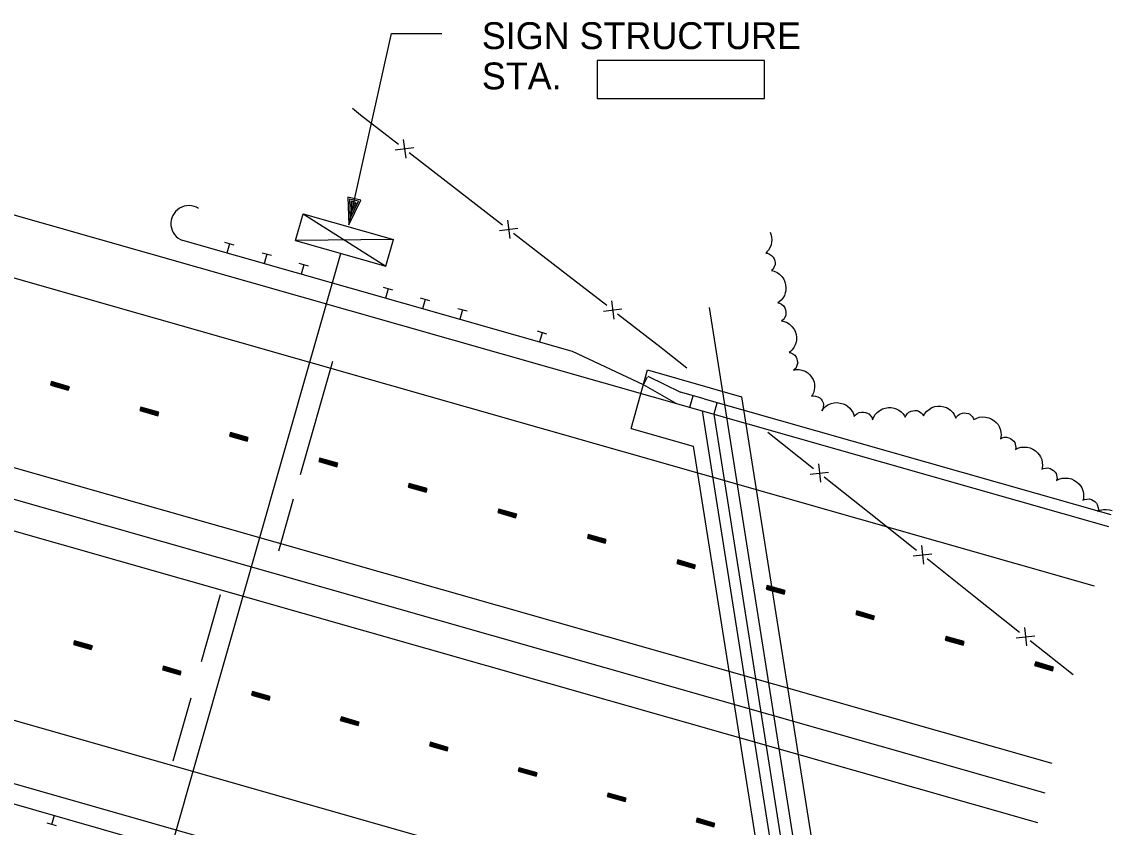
# Model space of a CAD drawing. Extents: x 640117 to 642655, y 297247 to 298435.
# Drawn here: x 641580.9 to 641702.7, y 298034.9 to 298124.9 of the extents above; entities that cross this region are included whole.
import ezdxf

# ---------------------------------------------------------------- set-up
doc = ezdxf.new("R2010")
doc.units = 0
for name, color, linetype in [('2', 7, 'Continuous'), ('20', 7, 'Continuous'), ('21', 7, 'Continuous'), ('26', 7, 'Continuous'), ('27', 7, 'Continuous'), ('36', 7, 'Continuous'), ('43', 7, 'Continuous'), ('48', 7, 'Continuous'), ('50', 7, 'Continuous'), ('51', 7, 'Continuous'), ('52', 7, 'Continuous'), ('7', 7, 'Continuous')]:
    doc.layers.add(name, color=color, linetype=linetype)

msp = doc.modelspace()

# ---------------------------------------------------------------- linework, layer by layer
at = {"layer": '2'}
msp.add_lwpolyline([(641645.15, 298116.37), (641663.87, 298116.37), (641663.87, 298120.62), (641645.15, 298120.62)], close=True, dxfattribs=at)
at = {"layer": '20'}
for points in [[(641664.48, 298101.43), (641664.57, 298101.21), (641664.65, 298100.88), (641664.69, 298100.56), (641664.66, 298100.33), (641664.59, 298100.01), (641664.46, 298099.69), (641664.3, 298099.43), (641664.13, 298099.23), (641664, 298099.1), (641664.18, 298099.08), (641664.42, 298098.99), (641664.64, 298098.84), (641664.82, 298098.64), (641664.93, 298098.45), (641665, 298098.24), (641665.05, 298097.99), (641665.04, 298097.81), (641664.92, 298097.47), (641664.83, 298097.29), (641664.66, 298097.14)], [(641664.66, 298097.14), (641664.95, 298097.06), (641665.28, 298096.91), (641665.53, 298096.73), (641665.8, 298096.46), (641666.01, 298096.17), (641666.14, 298095.88), (641666.22, 298095.54), (641666.26, 298095.21), (641666.25, 298094.88), (641666.19, 298094.66), (641666.08, 298094.36), (641665.91, 298094.06), (641665.71, 298093.82), (641665.51, 298093.64), (641665.37, 298093.54), (641665.54, 298093.49), (641665.77, 298093.37), (641665.97, 298093.19), (641666.12, 298092.98), (641666.2, 298092.77), (641666.24, 298092.55), (641666.26, 298092.3), (641666.23, 298092.13), (641666.06, 298091.8), (641665.94, 298091.64), (641665.76, 298091.51)], [(641665.76, 298091.51), (641666.05, 298091.46), (641666.38, 298091.33), (641666.64, 298091.15), (641666.92, 298090.9), (641667.15, 298090.62), (641667.29, 298090.35), (641667.39, 298090.01), (641667.43, 298089.69), (641667.44, 298089.37), (641667.4, 298089.14), (641667.29, 298088.84), (641667.13, 298088.54), (641666.95, 298088.29), (641666.76, 298088.11), (641666.61, 298088), (641666.79, 298087.96), (641667.03, 298087.85), (641667.24, 298087.69), (641667.39, 298087.48), (641667.49, 298087.28), (641667.53, 298087.07), (641667.57, 298086.83), (641667.53, 298086.65), (641667.39, 298086.32), (641667.28, 298086.16), (641667.1, 298086.02)], [(641667.1, 298086.02), (641667.39, 298086.07), (641667.74, 298086.08), (641668.05, 298086.01), (641668.4, 298085.88), (641668.71, 298085.7), (641668.93, 298085.5), (641669.13, 298085.23), (641669.29, 298084.95), (641669.41, 298084.66), (641669.45, 298084.43), (641669.46, 298084.12), (641669.42, 298083.79), (641669.33, 298083.49), (641669.22, 298083.26), (641669.12, 298083.11), (641669.3, 298083.13), (641669.56, 298083.11), (641669.81, 298083.04), (641670.03, 298082.91), (641670.18, 298082.76), (641670.3, 298082.59), (641670.41, 298082.37), (641670.45, 298082.2), (641670.42, 298081.84), (641670.38, 298081.65), (641670.26, 298081.47)], [(641670.26, 298081.47), (641670.43, 298081.7), (641670.69, 298081.96), (641670.95, 298082.13), (641671.3, 298082.28), (641671.66, 298082.37), (641671.98, 298082.39), (641672.33, 298082.34), (641672.65, 298082.25), (641672.95, 298082.13), (641673.14, 298081.99), (641673.38, 298081.78), (641673.6, 298081.51), (641673.75, 298081.24), (641673.85, 298081), (641673.89, 298080.82), (641674, 298080.97), (641674.19, 298081.13), (641674.43, 298081.27), (641674.69, 298081.32), (641674.91, 298081.32), (641675.14, 298081.28), (641675.37, 298081.21), (641675.52, 298081.12), (641675.77, 298080.84), (641675.88, 298080.68), (641675.94, 298080.46)], [(641675.94, 298080.46), (641676.04, 298080.73), (641676.23, 298081.04), (641676.44, 298081.27), (641676.73, 298081.51), (641677.05, 298081.69), (641677.35, 298081.78), (641677.7, 298081.82), (641678.03, 298081.82), (641678.35, 298081.77), (641678.57, 298081.69), (641678.86, 298081.54), (641679.13, 298081.34), (641679.34, 298081.12), (641679.49, 298080.9), (641679.58, 298080.74), (641679.65, 298080.91), (641679.8, 298081.12), (641680, 298081.3), (641680.23, 298081.42), (641680.44, 298081.48), (641680.67, 298081.5), (641680.91, 298081.49), (641681.07, 298081.44), (641681.38, 298081.23), (641681.53, 298081.1), (641681.63, 298080.9)], [(641681.63, 298080.9), (641681.78, 298081.16), (641682.01, 298081.44), (641682.25, 298081.63), (641682.57, 298081.82), (641682.91, 298081.95), (641683.22, 298081.99), (641683.56, 298081.98), (641683.88, 298081.93), (641684.19, 298081.84), (641684.39, 298081.73), (641684.65, 298081.53), (641684.89, 298081.29), (641685.06, 298081.04), (641685.18, 298080.8), (641685.24, 298080.63), (641685.33, 298080.79), (641685.5, 298080.98), (641685.73, 298081.13), (641685.97, 298081.21), (641686.18, 298081.24), (641686.41, 298081.22), (641686.64, 298081.18), (641686.8, 298081.09), (641687.07, 298080.84), (641687.19, 298080.69), (641687.26, 298080.48)], [(641687.26, 298080.48), (641687.52, 298080.62), (641687.86, 298080.74), (641688.17, 298080.78), (641688.55, 298080.77), (641688.91, 298080.7), (641689.2, 298080.58), (641689.49, 298080.39), (641689.74, 298080.17), (641689.96, 298079.93), (641690.07, 298079.73), (641690.19, 298079.43), (641690.27, 298079.1), (641690.29, 298078.79), (641690.27, 298078.53), (641690.23, 298078.35), (641690.39, 298078.44), (641690.64, 298078.51), (641690.91, 298078.52), (641691.16, 298078.46), (641691.36, 298078.37), (641691.54, 298078.24), (641691.72, 298078.07), (641691.82, 298077.92), (641691.92, 298077.57), (641691.94, 298077.38), (641691.9, 298077.15)], [(641691.9, 298077.15), (641692.16, 298077.29), (641692.51, 298077.39), (641692.82, 298077.42), (641693.2, 298077.4), (641693.56, 298077.33), (641693.84, 298077.2), (641694.14, 298077), (641694.38, 298076.77), (641694.6, 298076.53), (641694.71, 298076.32), (641694.83, 298076.01), (641694.89, 298075.68), (641694.91, 298075.37), (641694.88, 298075.11), (641694.84, 298074.93), (641695, 298075.01), (641695.26, 298075.07), (641695.52, 298075.08), (641695.78, 298075.01), (641695.98, 298074.92), (641696.16, 298074.78), (641696.34, 298074.61), (641696.43, 298074.45), (641696.52, 298074.09), (641696.55, 298073.9), (641696.5, 298073.68)], [(641696.5, 298073.68), (641696.76, 298073.82), (641697.1, 298073.93), (641697.41, 298073.96), (641697.8, 298073.93), (641698.16, 298073.86), (641698.44, 298073.73), (641698.73, 298073.53), (641698.98, 298073.31), (641699.19, 298073.06), (641699.31, 298072.86), (641699.42, 298072.55), (641699.5, 298072.22), (641699.51, 298071.9), (641699.49, 298071.64), (641699.44, 298071.47), (641699.61, 298071.56), (641699.86, 298071.61), (641700.13, 298071.62), (641700.39, 298071.55), (641700.58, 298071.46), (641700.77, 298071.32), (641700.94, 298071.15), (641701.03, 298071), (641701.13, 298070.64), (641701.16, 298070.45), (641701.11, 298070.23)], [(641701.1, 298070.23), (641701.37, 298070.35), (641701.72, 298070.44), (641702.04, 298070.45), (641702.42, 298070.41), (641702.71, 298070.33)]]:
    msp.add_lwpolyline(points, dxfattribs=at)
at = {"layer": '21'}
for p, q in [((641623.51, 298111.78), (641623.78, 298109.71)), ((641622.61, 298110.62), (641624.68, 298110.88)), ((641635.14, 298102.77), (641635.4, 298100.71)), ((641634.24, 298101.61), (641636.3, 298101.88)), ((641646.77, 298093.77), (641647.03, 298091.71)), ((641645.87, 298092.6), (641647.93, 298092.87)), ((641669.88, 298075.54), (641670.11, 298073.48)), ((641668.96, 298074.39), (641671.03, 298074.63)), ((641681.39, 298066.4), (641681.63, 298064.33)), ((641680.48, 298065.25), (641682.54, 298065.49)), ((641692.91, 298057.26), (641693.15, 298055.19)), ((641691.99, 298056.1), (641694.06, 298056.34))]:
    msp.add_line(p, q, dxfattribs=at)
for points in [[(641617.82, 298115.27), (641618.74, 298114.54), (641622.97, 298111.26)], [(641624.18, 298110.33), (641629.44, 298106.25)], [(641629.44, 298106.25), (641634.6, 298102.26)], [(641635.82, 298101.32), (641641.08, 298097.25)], [(641641.08, 298097.25), (641646.23, 298093.26)], [(641647.44, 298092.32), (641652.32, 298088.55), (641652.7, 298088.24)], [(641652.7, 298088.24), (641655.17, 298086.28)], [(641664.22, 298079.09), (641669.33, 298075.04)], [(641670.52, 298074.09), (641675.74, 298069.95)], [(641675.74, 298069.95), (641680.84, 298065.89)], [(641682.04, 298064.95), (641687.25, 298060.81)], [(641687.25, 298060.81), (641692.36, 298056.75)], [(641693.56, 298055.8), (641698.33, 298052.01)]]:
    msp.add_lwpolyline(points, dxfattribs=at)
at = {"layer": '26'}
for p, q in [((641519.29, 298120.67), (641656.91, 298081.45)), ((641517.16, 298114.21), (641700.7, 298061.92)), ((641510.78, 298094.85), (641695.96, 298042.08)), ((641508.65, 298088.39), (641694.38, 298035.47)), ((641502.27, 298069.03), (641689.65, 298015.64)), ((641500.14, 298062.57), (641667.43, 298014.9))]:
    msp.add_line(p, q, dxfattribs=at)
at = {"layer": '27'}
for p, q in [((641642.42, 298088.1), (641598.87, 298100.51)), ((641604.62, 298099.98), (641603.58, 298100.28)), ((641604.1, 298100.13), (641603.81, 298099.09)), ((641608.77, 298098.81), (641607.73, 298099.1)), ((641608.25, 298098.96), (641607.96, 298097.92)), ((641612.92, 298097.64), (641611.88, 298097.93)), ((641612.4, 298097.79), (641612.11, 298096.75)), ((641622.33, 298094.94), (641621.29, 298095.23)), ((641621.81, 298095.09), (641621.52, 298094.05)), ((641626.48, 298093.77), (641625.44, 298094.06)), ((641625.96, 298093.91), (641625.67, 298092.87)), ((641630.63, 298092.59), (641629.59, 298092.88)), ((641630.11, 298092.74), (641629.82, 298091.7)), ((641639.54, 298090.05), (641638.5, 298090.35)), ((641639.02, 298090.2), (641638.73, 298089.16)), ((641650.34, 298084.37), (641642.42, 298088.1)), ((641584.25, 298035.24), (641584.54, 298036.27)), ((641584.76, 298035.09), (641583.73, 298035.39))]:
    msp.add_line(p, q, dxfattribs=at)
msp.add_lwpolyline([(641563.87, 298042.17), (641648.86, 298017.76), (641660.03, 298015.97)], dxfattribs=at)
msp.add_ellipse((641599.55, 298102.39), major_axis=(1.15, 1.64), ratio=0.999995, start_param=0.035909, end_param=3.402363, dxfattribs=at)
at = {"layer": '36'}
msp.add_line((641509.71, 298091.62), (641695.17, 298038.78), dxfattribs=at)
at = {"layer": '43'}
for p, q in [((641611.48, 298100.5), (641612.33, 298103.47)), ((641612.32, 298103.48), (641622.41, 298100.6)), ((641612.32, 298103.48), (641621.56, 298097.62)), ((641622.41, 298100.6), (641611.48, 298100.5)), ((641611.48, 298100.5), (641621.56, 298097.62)), ((641621.56, 298097.62), (641622.41, 298100.6)), ((641596.52, 298028.88), (641616.52, 298099.06)), ((641612.03, 298074.34), (641615.65, 298087.03)), ((641609.6, 298065.81), (641611.26, 298071.65)), ((641600.96, 298053.45), (641603.1, 298060.95)), ((641597.8, 298042.34), (641599.81, 298049.41))]:
    msp.add_line(p, q, dxfattribs=at)
at = {"layer": '48'}
for points in [[(641584.08, 298084.34), (641586.08, 298083.77), (641586.2, 298084.16), (641584.2, 298084.73)], [(641584.14, 298084.37), (641586.05, 298083.82), (641586.14, 298084.14), (641584.22, 298084.68)], [(641584.2, 298084.4), (641586.02, 298083.88), (641586.08, 298084.11), (641584.26, 298084.62)], [(641584.24, 298084.42), (641585.99, 298083.92), (641586.03, 298084.08), (641584.29, 298084.58)], [(641584.28, 298084.45), (641585.97, 298083.96), (641586, 298084.05), (641584.31, 298084.54)], [(641584.31, 298084.47), (641585.95, 298084), (641585.96, 298084.03), (641584.32, 298084.5)], [(641594.08, 298081.49), (641596.08, 298080.92), (641596.19, 298081.32), (641594.19, 298081.89)], [(641594.13, 298081.51), (641596.04, 298080.97), (641596.13, 298081.28), (641594.22, 298081.83)], [(641594.19, 298081.55), (641596.01, 298081.03), (641596.08, 298081.25), (641594.25, 298081.77)], [(641594.24, 298081.58), (641595.99, 298081.07), (641596.03, 298081.23), (641594.28, 298081.73)], [(641594.28, 298081.6), (641595.97, 298081.12), (641596, 298081.21), (641594.3, 298081.69)], [(641594.31, 298081.62), (641595.95, 298081.15), (641595.96, 298081.19), (641594.32, 298081.65)], [(641604.08, 298078.63), (641606.07, 298078.07), (641606.19, 298078.47), (641604.19, 298079.04)], [(641604.13, 298078.67), (641606.04, 298078.12), (641606.13, 298078.44), (641604.22, 298078.98)], [(641604.19, 298078.7), (641606.01, 298078.18), (641606.08, 298078.4), (641604.25, 298078.93)], [(641604.23, 298078.73), (641605.99, 298078.23), (641606.03, 298078.38), (641604.28, 298078.88)], [(641604.28, 298078.75), (641605.96, 298078.27), (641605.99, 298078.36), (641604.3, 298078.84)], [(641604.31, 298078.77), (641605.94, 298078.3), (641605.95, 298078.34), (641604.32, 298078.8)], [(641614.07, 298075.79), (641616.07, 298075.22), (641616.19, 298075.62), (641614.19, 298076.19)], [(641614.13, 298075.82), (641616.04, 298075.28), (641616.13, 298075.59), (641614.21, 298076.13)], [(641614.18, 298075.85), (641616.01, 298075.33), (641616.07, 298075.55), (641614.25, 298076.08)], [(641614.23, 298075.88), (641615.98, 298075.38), (641616.02, 298075.53), (641614.27, 298076.03)], [(641614.27, 298075.9), (641615.96, 298075.42), (641615.99, 298075.51), (641614.29, 298075.99)], [(641614.31, 298075.92), (641615.94, 298075.45), (641615.95, 298075.49), (641614.31, 298075.96)], [(641624.07, 298072.94), (641626.07, 298072.37), (641626.18, 298072.77), (641624.18, 298073.34)], [(641624.12, 298072.97), (641626.04, 298072.43), (641626.13, 298072.74), (641624.21, 298073.28)], [(641624.18, 298073), (641626, 298072.48), (641626.07, 298072.71), (641624.25, 298073.23)], [(641624.23, 298073.03), (641625.98, 298072.53), (641626.02, 298072.68), (641624.27, 298073.18)], [(641624.27, 298073.05), (641625.96, 298072.57), (641625.98, 298072.66), (641624.29, 298073.14)], [(641624.3, 298073.07), (641625.94, 298072.61), (641625.95, 298072.64), (641624.31, 298073.11)], [(641634.06, 298070.09), (641636.06, 298069.52), (641636.18, 298069.92), (641634.18, 298070.49)], [(641634.12, 298070.12), (641636.03, 298069.57), (641636.12, 298069.89), (641634.21, 298070.44)], [(641634.18, 298070.15), (641636, 298069.63), (641636.07, 298069.86), (641634.24, 298070.38)], [(641634.22, 298070.18), (641635.97, 298069.68), (641636.02, 298069.83), (641634.27, 298070.33)], [(641634.26, 298070.21), (641635.96, 298069.72), (641635.98, 298069.81), (641634.29, 298070.29)], [(641634.3, 298070.23), (641635.94, 298069.76), (641635.94, 298069.79), (641634.31, 298070.26)], [(641644.07, 298067.25), (641646.06, 298066.67), (641646.17, 298067.07), (641644.18, 298067.64)], [(641644.11, 298067.27), (641646.03, 298066.73), (641646.12, 298067.04), (641644.21, 298067.59)], [(641644.17, 298067.31), (641646, 298066.79), (641646.06, 298067.01), (641644.24, 298067.53)], [(641644.22, 298067.33), (641645.97, 298066.83), (641646.02, 298066.99), (641644.27, 298067.49)], [(641644.26, 298067.35), (641645.95, 298066.87), (641645.97, 298066.96), (641644.29, 298067.45)], [(641644.3, 298067.38), (641645.93, 298066.91), (641645.94, 298066.94), (641644.31, 298067.41)], [(641654.06, 298064.4), (641656.05, 298063.83), (641656.17, 298064.23), (641654.17, 298064.8)], [(641654.11, 298064.42), (641656.03, 298063.88), (641656.12, 298064.19), (641654.2, 298064.74)], [(641654.17, 298064.46), (641656, 298063.94), (641656.06, 298064.17), (641654.23, 298064.68)], [(641654.21, 298064.49), (641655.97, 298063.99), (641656.01, 298064.14), (641654.26, 298064.63)], [(641654.25, 298064.51), (641655.95, 298064.03), (641655.97, 298064.11), (641654.28, 298064.6)], [(641654.29, 298064.52), (641655.92, 298064.06), (641655.94, 298064.1), (641654.3, 298064.56)], [(641664.06, 298061.54), (641666.06, 298060.98), (641666.17, 298061.38), (641664.17, 298061.95)], [(641664.11, 298061.58), (641666.02, 298061.03), (641666.11, 298061.35), (641664.2, 298061.89)], [(641664.17, 298061.61), (641665.99, 298061.09), (641666.06, 298061.31), (641664.23, 298061.84)], [(641664.22, 298061.64), (641665.96, 298061.14), (641666.01, 298061.29), (641664.26, 298061.78)], [(641664.26, 298061.66), (641665.94, 298061.18), (641665.97, 298061.27), (641664.28, 298061.75)], [(641664.29, 298061.68), (641665.92, 298061.21), (641665.93, 298061.25), (641664.3, 298061.71)], [(641674.05, 298058.7), (641676.05, 298058.13), (641676.16, 298058.53), (641674.17, 298059.1)], [(641674.11, 298058.73), (641676.01, 298058.18), (641676.11, 298058.5), (641674.19, 298059.04)], [(641674.17, 298058.76), (641675.99, 298058.24), (641676.05, 298058.47), (641674.23, 298058.99)], [(641674.21, 298058.78), (641675.96, 298058.29), (641676.01, 298058.44), (641674.25, 298058.94)], [(641674.25, 298058.81), (641675.94, 298058.33), (641675.97, 298058.42), (641674.28, 298058.9)], [(641674.29, 298058.83), (641675.92, 298058.36), (641675.93, 298058.4), (641674.29, 298058.87)], [(641586.66, 298055.36), (641588.65, 298054.79), (641588.77, 298055.19), (641586.78, 298055.75)], [(641586.71, 298055.39), (641588.62, 298054.85), (641588.71, 298055.16), (641586.8, 298055.7)], [(641586.77, 298055.42), (641588.59, 298054.9), (641588.65, 298055.13), (641586.83, 298055.64)], [(641586.82, 298055.45), (641588.56, 298054.95), (641588.6, 298055.1), (641586.86, 298055.59)], [(641586.86, 298055.46), (641588.54, 298054.99), (641588.56, 298055.08), (641586.89, 298055.56)], [(641586.9, 298055.48), (641588.52, 298055.02), (641588.53, 298055.06), (641586.91, 298055.52)], [(641684.05, 298055.85), (641686.05, 298055.28), (641686.16, 298055.68), (641684.16, 298056.25)], [(641684.1, 298055.88), (641686.02, 298055.33), (641686.11, 298055.65), (641684.19, 298056.2)], [(641684.16, 298055.91), (641685.99, 298055.39), (641686.05, 298055.62), (641684.23, 298056.14)], [(641684.21, 298055.94), (641685.96, 298055.44), (641686, 298055.59), (641684.26, 298056.09)], [(641684.25, 298055.96), (641685.93, 298055.48), (641685.96, 298055.57), (641684.27, 298056.05)], [(641684.28, 298055.98), (641685.92, 298055.52), (641685.92, 298055.55), (641684.29, 298056.02)], [(641596.6, 298052.52), (641598.59, 298051.96), (641598.7, 298052.35), (641596.71, 298052.93)], [(641596.66, 298052.56), (641598.56, 298052.01), (641598.65, 298052.33), (641596.74, 298052.87)], [(641596.71, 298052.58), (641598.53, 298052.07), (641598.59, 298052.29), (641596.78, 298052.81)], [(641694.04, 298053), (641696.04, 298052.43), (641696.16, 298052.83), (641694.16, 298053.4)], [(641694.1, 298053.04), (641696.01, 298052.49), (641696.1, 298052.8), (641694.18, 298053.35)], [(641694.15, 298053.06), (641695.98, 298052.55), (641696.04, 298052.77), (641694.22, 298053.29)], [(641694.2, 298053.09), (641695.96, 298052.59), (641695.99, 298052.74), (641694.25, 298053.24)], [(641694.24, 298053.11), (641695.94, 298052.63), (641695.96, 298052.72), (641694.27, 298053.2)], [(641694.28, 298053.13), (641695.91, 298052.67), (641695.93, 298052.7), (641694.29, 298053.16)], [(641596.76, 298052.61), (641598.5, 298052.12), (641598.54, 298052.27), (641596.81, 298052.76)], [(641596.8, 298052.63), (641598.47, 298052.15), (641598.5, 298052.24), (641596.82, 298052.72)], [(641596.83, 298052.66), (641598.46, 298052.19), (641598.47, 298052.23), (641596.84, 298052.69)], [(641606.54, 298049.7), (641608.52, 298049.13), (641608.64, 298049.53), (641606.65, 298050.09)], [(641606.59, 298049.72), (641608.5, 298049.18), (641608.58, 298049.49), (641606.68, 298050.03)], [(641606.65, 298049.76), (641608.46, 298049.24), (641608.53, 298049.46), (641606.71, 298049.98)], [(641606.69, 298049.79), (641608.43, 298049.28), (641608.48, 298049.44), (641606.74, 298049.93)], [(641606.73, 298049.8), (641608.41, 298049.33), (641608.44, 298049.41), (641606.76, 298049.89)], [(641606.77, 298049.82), (641608.4, 298049.36), (641608.41, 298049.39), (641606.78, 298049.85)], [(641616.47, 298046.86), (641618.46, 298046.29), (641618.58, 298046.69), (641616.59, 298047.26)], [(641616.53, 298046.89), (641618.43, 298046.35), (641618.52, 298046.66), (641616.62, 298047.2)], [(641616.59, 298046.92), (641618.4, 298046.4), (641618.46, 298046.63), (641616.65, 298047.15)], [(641616.64, 298046.95), (641618.38, 298046.45), (641618.42, 298046.61), (641616.68, 298047.1)], [(641616.67, 298046.97), (641618.35, 298046.49), (641618.38, 298046.58), (641616.7, 298047.06)], [(641616.71, 298046.99), (641618.34, 298046.53), (641618.34, 298046.57), (641616.72, 298047.03)], [(641626.42, 298044.03), (641628.4, 298043.46), (641628.51, 298043.86), (641626.53, 298044.43)], [(641626.47, 298044.06), (641628.37, 298043.52), (641628.46, 298043.83), (641626.56, 298044.37)], [(641626.53, 298044.09), (641628.34, 298043.58), (641628.4, 298043.8), (641626.59, 298044.32)], [(641626.57, 298044.12), (641628.31, 298043.62), (641628.35, 298043.77), (641626.62, 298044.27)], [(641626.61, 298044.14), (641628.29, 298043.66), (641628.32, 298043.75), (641626.64, 298044.23)], [(641626.65, 298044.16), (641628.27, 298043.7), (641628.28, 298043.73), (641626.66, 298044.19)], [(641636.35, 298041.2), (641638.34, 298040.63), (641638.46, 298041.03), (641636.46, 298041.59)], [(641636.41, 298041.23), (641638.31, 298040.68), (641638.4, 298041), (641636.49, 298041.54)], [(641636.46, 298041.26), (641638.27, 298040.74), (641638.34, 298040.97), (641636.53, 298041.48)], [(641636.51, 298041.29), (641638.25, 298040.79), (641638.29, 298040.94), (641636.55, 298041.44)], [(641636.55, 298041.31), (641638.23, 298040.83), (641638.25, 298040.92), (641636.57, 298041.4)], [(641636.59, 298041.33), (641638.21, 298040.86), (641638.22, 298040.9), (641636.6, 298041.36)], [(641646.29, 298038.36), (641648.28, 298037.8), (641648.39, 298038.2), (641646.4, 298038.76)], [(641646.34, 298038.4), (641648.24, 298037.86), (641648.34, 298038.17), (641646.43, 298038.71)], [(641646.4, 298038.43), (641648.22, 298037.91), (641648.28, 298038.13), (641646.46, 298038.65)], [(641646.45, 298038.46), (641648.19, 298037.96), (641648.24, 298038.11), (641646.49, 298038.6)], [(641646.49, 298038.47), (641648.16, 298038), (641648.19, 298038.09), (641646.51, 298038.56)], [(641646.52, 298038.5), (641648.15, 298038.03), (641648.16, 298038.07), (641646.53, 298038.53)], [(641656.23, 298035.53), (641658.21, 298034.97), (641658.33, 298035.36), (641656.34, 298035.93)], [(641656.28, 298035.57), (641658.19, 298035.02), (641658.27, 298035.34), (641656.37, 298035.87)], [(641656.34, 298035.59), (641658.15, 298035.08), (641658.22, 298035.3), (641656.4, 298035.82)], [(641656.38, 298035.62), (641658.12, 298035.13), (641658.17, 298035.28), (641656.43, 298035.77)], [(641656.43, 298035.64), (641658.1, 298035.16), (641658.13, 298035.25), (641656.45, 298035.73)], [(641656.46, 298035.66), (641658.09, 298035.2), (641658.1, 298035.24), (641656.47, 298035.7)]]:
    msp.add_lwpolyline(points, close=True, dxfattribs=at)
at = {"layer": '50'}
msp.add_line((641657.68, 298093.03), (641671.65, 298004.62), dxfattribs=at)
at = {"layer": '51'}
for p, q in [((641648.95, 298079.5), (641650.81, 298086.03)), ((641650.81, 298086.03), (641661.3, 298083.04)), ((641650.34, 298084.37), (641650.78, 298085.28)), ((641650.82, 298085.35), (641654.49, 298083.57)), ((641653.98, 298082.29), (641650.34, 298084.37)), ((641654.43, 298083.59), (641657.09, 298082.83)), ((641655.85, 298083.1), (641655.5, 298081.85)), ((641657.13, 298082.82), (641702.57, 298069.87)), ((641658.54, 298082.33), (641658.19, 298081.09)), ((641661.3, 298083.04), (641672.28, 298013.54)), ((641656.91, 298081.45), (641667.43, 298014.9)), ((641656.91, 298081.45), (641702.28, 298068.53)), ((641658.19, 298081.09), (641668.71, 298014.54)), ((641648.95, 298079.5), (641655.91, 298077.51)), ((641655.91, 298077.51), (641665.03, 298019.81))]:
    msp.add_line(p, q, dxfattribs=at)
at = {"layer": '52'}
for p, q in [((641617.32, 298105.33), (641617.42, 298102.24)), ((641618.78, 298105.01), (641617.32, 298105.33)), ((641617.42, 298102.24), (641618.78, 298105.01)), ((641617.5, 298105.11), (641617.58, 298102.95)), ((641618.52, 298104.89), (641617.5, 298105.11)), ((641617.58, 298102.95), (641618.52, 298104.89)), ((641617.69, 298104.89), (641617.73, 298103.67)), ((641618.26, 298104.76), (641617.69, 298104.89)), ((641617.73, 298103.67), (641618.26, 298104.76)), ((641617.87, 298104.77), (641617.88, 298104.39)), ((641617.88, 298104.39), (641618.04, 298104.72))]:
    msp.add_line(p, q, dxfattribs=at)
at = {"layer": '7'}
for p, q in [((641617.42, 298102.24), (641622.19, 298123.63)), ((641622.19, 298123.63), (641627.83, 298123.63))]:
    msp.add_line(p, q, dxfattribs=at)

# ---------------------------------------------------------------- texts
at = {"layer": '2'}
for s, height, p in [('SIGN STRUCTURE', 2.9999, (641632.28, 298121.89)), ('STA.', 3, (641632.28, 298117.39))]:
    msp.add_text(s, height=height, dxfattribs=at).set_placement(p)

doc.saveas('drawing.dxf')
